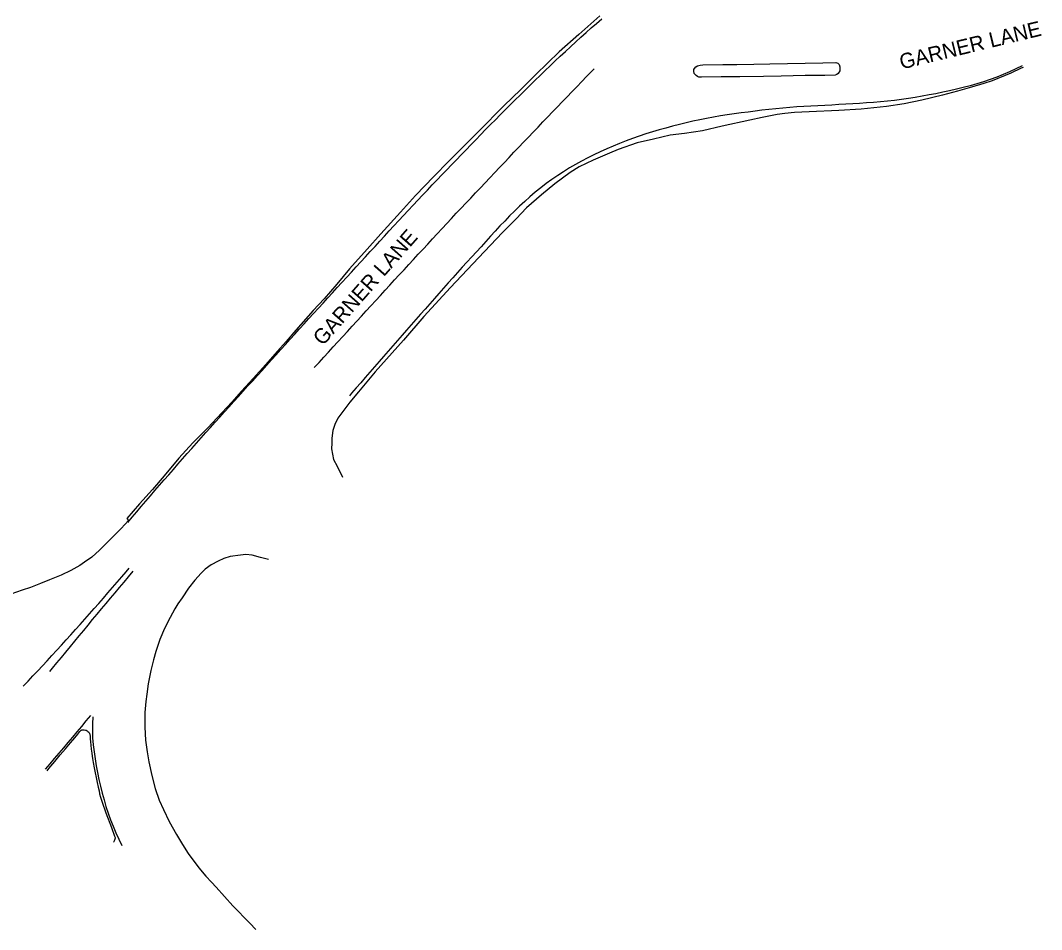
# Model space of a CAD drawing. Extents: x 1961683 to 1977751, y 798292 to 805767.
# Drawn here: x 1971882.7 to 1972247.5, y 802391.1 to 802715.6 of the extents above; entities that cross this region are included whole.
import ezdxf

# ---------------------------------------------------------------- set-up
doc = ezdxf.new("R2010")
doc.units = 0
for name, color, linetype in [('RD_EX_Conc', 7, 'Continuous'), ('RD_EX_Road', 7, 'Continuous'), ('RD_EX_Road_Paint', 7, 'Continuous'), ('RD_TX_RoadID', 7, 'Continuous')]:
    doc.layers.add(name, color=color, linetype=linetype)

msp = doc.modelspace()

# ---------------------------------------------------------------- linework, layer by layer
at = {"layer": 'RD_EX_Conc'}
for points in [[(1972150.42, 802700.16), (1972169.39, 802700.53), (1972173.93, 802700.6), (1972174.63, 802700.35), (1972175.13, 802699.87), (1972175.45, 802699), (1972175.42, 802697.57), (1972174.81, 802696.62), (1972174.29, 802696.26), (1972173.7, 802696.08), (1972170.04, 802695.96), (1972163.06, 802695.9), (1972154.48, 802695.75), (1972148.1, 802695.65), (1972139.65, 802695.51), (1972132.99, 802695.44), (1972125.99, 802695.32), (1972125.09, 802695.42), (1972124.51, 802695.65), (1972124.05, 802695.95), (1972123.69, 802696.26), (1972123.36, 802696.64), (1972123.2, 802697.56), (1972123.25, 802698.12), (1972123.48, 802698.51), (1972123.97, 802699.03), (1972124.56, 802699.39), (1972125.47, 802699.65), (1972126.52, 802699.79), (1972133.59, 802699.89), (1972138.58, 802699.94), (1972144.63, 802700.05), (1972150.42, 802700.16)], [(1971892.27, 802447.78), (1971892.93, 802448.58), (1971895.04, 802451.1), (1971896.99, 802453.42), (1971898.83, 802455.59), (1971900.59, 802457.67), (1971902.12, 802459.48), (1971903.25, 802460.87), (1971904, 802461.77), (1971904.37, 802462.16), (1971904.46, 802462.22), (1971904.57, 802462.27), (1971904.68, 802462.31), (1971904.81, 802462.33), (1971905.12, 802462.35), (1971905.54, 802462.34), (1971905.93, 802462.29), (1971906.07, 802462.26), (1971906.18, 802462.23), (1971906.28, 802462.19), (1971906.54, 802462.03), (1971906.86, 802461.79), (1971907.12, 802461.54), (1971907.31, 802461.28), (1971907.45, 802461.02), (1971907.51, 802460.88), (1971907.56, 802460.71), (1971907.64, 802460.09), (1971907.69, 802459.16), (1971907.78, 802458.07), (1971907.89, 802456.84), (1971908.03, 802455.49), (1971908.2, 802454.07), (1971908.34, 802452.95), (1971908.48, 802452.07), (1971908.72, 802450.71), (1971909.05, 802448.84), (1971909.41, 802447.02), (1971909.79, 802445.31), (1971910.17, 802443.58), (1971910.54, 802441.87), (1971910.82, 802440.55), (1971911.03, 802439.56), (1971911.34, 802438.33), (1971911.88, 802436.51), (1971913.24, 802432.77), (1971915.26, 802427.5), (1971916.4, 802424.45), (1971916.55, 802423.98), (1971916.53, 802423.71), (1971916.47, 802423.33), (1971916.36, 802422.93), (1971916.28, 802422.75), (1971916.19, 802422.59), (1971916.08, 802422.42), (1971915.93, 802422.26)]]:
    msp.add_lwpolyline(points, dxfattribs=at)
at = {"layer": 'RD_EX_Road'}
for points in [[(1972089.73, 802717.27), (1972082.21, 802710.64), (1972075.12, 802704.38), (1972066.86, 802696.35), (1972061.44, 802690.94), (1972055.38, 802685.15), (1972046.52, 802676.14), (1972041.26, 802670.85), (1972035.73, 802665.36), (1972030.45, 802659.9), (1972023.89, 802653.11), (1972018.52, 802647.16), (1972011.47, 802639.43), (1972006.53, 802633.94), (1972000.33, 802626.97), (1971995.74, 802621.41), (1971991.24, 802616.28), (1971987.32, 802612.05), (1971981.09, 802604.99), (1971977.62, 802601), (1971974.41, 802597.42), (1971970.4, 802592.81), (1971965.83, 802587.79), (1971961.76, 802583.21), (1971958.22, 802579.29), (1971954.73, 802575.5), (1971949.67, 802570.21), (1971944.27, 802564.78), (1971939.35, 802559.29), (1971934.13, 802552.99), (1971929.96, 802548.17), (1971925.27, 802543), (1971920.74, 802537.76), (1971921.36, 802537.08), (1971918.74, 802534.18), (1971914.59, 802530.02), (1971911.02, 802526.5), (1971908.26, 802524.03), (1971905.66, 802522.22), (1971904, 802521.07), (1971900.69, 802519.2), (1971897.34, 802517.6), (1971893.13, 802515.87), (1971889.91, 802514.62), (1971886.37, 802513.22), (1971883.34, 802512.23), (1971879.33, 802510.83)], [(1972240.83, 802698.83), (1972240.22, 802698.52), (1972236.48, 802696.75), (1972229.76, 802694.1), (1972226.8, 802693.07), (1972222.41, 802691.75), (1972217.42, 802690.37), (1972212.12, 802688.92), (1972204.72, 802687.15), (1972198.34, 802685.84), (1972192.13, 802684.88), (1972183.02, 802683.98), (1972175.09, 802683.45), (1972164.46, 802683.01), (1972159.24, 802682.73), (1972155.78, 802682.43), (1972153.02, 802682.07), (1972147.61, 802681), (1972143.25, 802680), (1972133.33, 802677.9), (1972126.35, 802676.26), (1972119.88, 802675.2), (1972114.8, 802674.67), (1972108.81, 802673.19), (1972103.06, 802671.89), (1972096.25, 802669.57), (1972093.16, 802668.19), (1972087.33, 802665.7), (1972082.26, 802663.32), (1972079.11, 802661.33), (1972073.65, 802657.27), (1972068.86, 802653.4), (1972063.52, 802648.66), (1972059.77, 802644.82), (1972054.97, 802639.85), (1972046.35, 802630.89), (1972036.29, 802620.31), (1972026.86, 802609.9), (1972019.52, 802601.5), (1972009.49, 802590.17), (1972003.48, 802583.02), (1972000.42, 802579.3), (1971998.62, 802576.99), (1971996.16, 802573.61), (1971995.04, 802571.42), (1971994.37, 802569.23), (1971993.91, 802566.46), (1971993.91, 802564.74), (1971993.89, 802562.63), (1971994.53, 802558.87), (1971995.86, 802556.45), (1971997.75, 802552.59)], [(1971971.38, 802523.13), (1971968.49, 802523.87), (1971965.46, 802524.69), (1971963.19, 802524.98), (1971961.35, 802524.77), (1971957.65, 802524.21), (1971955.45, 802523.51), (1971953.31, 802522.59), (1971950.86, 802521.24), (1971948.68, 802519.71), (1971947.27, 802518.3), (1971944.98, 802515.81), (1971942.77, 802512.91), (1971940.46, 802509.54), (1971939, 802507.31), (1971937.9, 802505.51), (1971936.18, 802502.43), (1971934.22, 802498.52), (1971932.59, 802494.67), (1971931.14, 802490.38), (1971930.3, 802487.36), (1971929.37, 802483.6), (1971928.37, 802478.82), (1971927.83, 802475.05), (1971927.52, 802472.45), (1971927.23, 802468.58), (1971927.19, 802463.35), (1971927.46, 802458.66), (1971928, 802454.53), (1971928.6, 802450.92), (1971929.71, 802446.07), (1971930.89, 802441.39), (1971932.27, 802437.3), (1971933.81, 802433.87), (1971935.85, 802429.69), (1971938.49, 802424.94), (1971940.58, 802421.42), (1971942.7, 802418.19), (1971946.45, 802413.14), (1971948.98, 802410.07), (1971951.01, 802407.98), (1971952.64, 802406.18), (1971958.66, 802399.51), (1971964.69, 802393.35), (1971966.82, 802391.06)]]:
    msp.add_lwpolyline(points, dxfattribs=at)
at = {"layer": 'RD_EX_Road_Paint'}
for points in [[(1971921.1, 802536.35), (1971922.7, 802538.27), (1971924.31, 802540.19), (1971925.91, 802542.11), (1971927.53, 802544.01), (1971929.15, 802545.91), (1971930.79, 802547.8), (1971932.44, 802549.68), (1971934.08, 802551.56), (1971935.73, 802553.44), (1971937.37, 802555.32), (1971939.01, 802557.21), (1971940.66, 802559.09), (1971942.3, 802560.97), (1971943.94, 802562.85), (1971945.59, 802564.73), (1971947.25, 802566.6), (1971948.92, 802568.46), (1971950.58, 802570.33), (1971952.25, 802572.18), (1971953.93, 802574.03), (1971955.62, 802575.87), (1971957.3, 802577.72), (1971958.99, 802579.57), (1971960.67, 802581.41), (1971962.35, 802583.26), (1971964.02, 802585.12), (1971965.69, 802586.97), (1971967.36, 802588.83), (1971969.03, 802590.69), (1971970.7, 802592.54), (1971972.37, 802594.4), (1971974.04, 802596.25), (1971975.72, 802598.1), (1971977.4, 802599.95), (1971979.08, 802601.8), (1971980.75, 802603.65), (1971982.43, 802605.49), (1971984.11, 802607.34), (1971985.79, 802609.19), (1971987.47, 802611.03), (1971989.15, 802612.88), (1971990.84, 802614.72), (1971992.52, 802616.56), (1971994.21, 802618.4), (1971995.9, 802620.24), (1971997.58, 802622.08), (1971999.27, 802623.92), (1972000.96, 802625.76), (1972002.64, 802627.6), (1972004.33, 802629.44), (1972006.01, 802631.28), (1972007.7, 802633.12), (1972009.39, 802634.96), (1972011.07, 802636.8), (1972012.76, 802638.64), (1972014.44, 802640.48), (1972016.14, 802642.32), (1972017.84, 802644.14), (1972019.55, 802645.96), (1972021.25, 802647.78), (1972022.96, 802649.61), (1972024.66, 802651.43), (1972026.37, 802653.25), (1972028.08, 802655.06), (1972029.81, 802656.87), (1972031.54, 802658.67), (1972033.27, 802660.47), (1972034.99, 802662.27), (1972036.72, 802664.07), (1972038.45, 802665.87), (1972040.19, 802667.67), (1972041.92, 802669.46), (1972043.66, 802671.25), (1972045.39, 802673.05), (1972047.13, 802674.84), (1972048.86, 802676.64), (1972050.62, 802678.41), (1972052.38, 802680.19), (1972054.13, 802681.96), (1972055.91, 802683.71), (1972057.69, 802685.46), (1972059.46, 802687.22), (1972061.24, 802688.97), (1972063.01, 802690.72), (1972064.78, 802692.48), (1972066.56, 802694.24), (1972068.35, 802695.97), (1972070.14, 802697.71), (1972071.94, 802699.44), (1972073.74, 802701.16), (1972075.55, 802702.89), (1972077.39, 802704.57), (1972079.23, 802706.25), (1972081.08, 802707.93), (1972082.93, 802709.6), (1972084.79, 802711.27), (1972086.64, 802712.94), (1972088.53, 802714.58), (1972090.41, 802716.22)], [(1972240.56, 802699.36), (1972238.3, 802698.29), (1972236.03, 802697.25), (1972233.74, 802696.27), (1972231.42, 802695.33), (1972229.07, 802694.48), (1972226.7, 802693.7), (1972224.31, 802692.96), (1972221.9, 802692.31), (1972219.48, 802691.67), (1972217.06, 802691.08), (1972214.62, 802690.53), (1972212.18, 802690), (1972209.73, 802689.47), (1972207.28, 802689), (1972204.82, 802688.53), (1972202.35, 802688.15), (1972199.88, 802687.77), (1972197.41, 802687.42), (1972194.93, 802687.08), (1972192.45, 802686.79), (1972189.96, 802686.52), (1972187.47, 802686.33), (1972184.98, 802686.16), (1972182.48, 802686), (1972179.99, 802685.85), (1972177.49, 802685.7), (1972175, 802685.55), (1972172.5, 802685.41), (1972170.01, 802685.27), (1972167.51, 802685.14), (1972165.01, 802685.01), (1972162.52, 802684.87), (1972160.02, 802684.72), (1972157.53, 802684.55), (1972155.04, 802684.31), (1972152.56, 802684.07), (1972150.07, 802683.8), (1972147.59, 802683.53), (1972145.11, 802683.22), (1972142.63, 802682.91), (1972140.15, 802682.6), (1972137.68, 802682.26), (1972135.21, 802681.92), (1972132.74, 802681.5), (1972130.28, 802681.08), (1972127.83, 802680.61), (1972125.39, 802680.12), (1972122.95, 802679.6), (1972120.52, 802679.04), (1972118.1, 802678.44), (1972115.68, 802677.83), (1972113.26, 802677.21), (1972110.86, 802676.56), (1972108.47, 802675.83), (1972106.09, 802675.09), (1972103.73, 802674.29), (1972101.38, 802673.46), (1972099.05, 802672.58), (1972096.73, 802671.67), (1972094.42, 802670.72), (1972092.13, 802669.74), (1972089.85, 802668.73), (1972087.59, 802667.69), (1972085.35, 802666.59), (1972083.15, 802665.42), (1972080.96, 802664.22), (1972078.8, 802662.97), (1972076.71, 802661.6), (1972074.64, 802660.22), (1972072.56, 802658.83), (1972070.55, 802657.35), (1972068.58, 802655.82), (1972066.63, 802654.27), (1972064.73, 802652.66), (1972062.86, 802651), (1972061.03, 802649.31), (1972059.25, 802647.56), (1972057.48, 802645.8), (1972055.74, 802644.01), (1972054, 802642.23), (1972052.3, 802640.4), (1972050.63, 802638.55), (1972048.95, 802636.7), (1972047.27, 802634.85), (1972045.59, 802633.01), (1972043.91, 802631.17), (1972042.23, 802629.32), (1972040.55, 802627.48), (1972038.87, 802625.63), (1972037.22, 802623.77), (1972035.56, 802621.9), (1972033.9, 802620.04), (1972032.24, 802618.18), (1972030.58, 802616.31), (1972028.93, 802614.44), (1972027.28, 802612.57), (1972025.63, 802610.7), (1972023.98, 802608.83), (1972022.33, 802606.96), (1972020.68, 802605.09), (1972019.03, 802603.22), (1972017.38, 802601.35), (1972015.74, 802599.46), (1972014.11, 802597.58), (1972012.47, 802595.7), (1972010.83, 802593.82), (1972009.19, 802591.93), (1972007.56, 802590.05), (1972005.92, 802588.17), (1972004.28, 802586.29), (1972002.64, 802584.4), (1972001.01, 802582.52), (1972000.23, 802581.63)], [(1971987.71, 802591.71), (1971989.4, 802593.55), (1971991.09, 802595.39), (1971992.77, 802597.23), (1971994.46, 802599.07), (1971996.15, 802600.91), (1971997.84, 802602.75), (1971999.52, 802604.59), (1972001.21, 802606.42), (1972002.89, 802608.26), (1972004.58, 802610.1), (1972006.27, 802611.94), (1972007.95, 802613.78), (1972009.64, 802615.62), (1972011.32, 802617.46), (1972013.01, 802619.29), (1972014.7, 802621.13), (1972016.38, 802622.97), (1972018.07, 802624.81), (1972019.76, 802626.64), (1972021.46, 802628.48), (1972023.16, 802630.31), (1972024.85, 802632.14), (1972026.55, 802633.97), (1972028.25, 802635.8), (1972029.94, 802637.63), (1972031.64, 802639.46), (1972033.33, 802641.29), (1972035.03, 802643.12), (1972036.73, 802644.95), (1972038.43, 802646.77), (1972040.15, 802648.59), (1972041.86, 802650.4), (1972043.58, 802652.21), (1972045.29, 802654.02), (1972047.01, 802655.84), (1972048.73, 802657.65), (1972050.44, 802659.46), (1972052.16, 802661.28), (1972053.88, 802663.09), (1972055.59, 802664.9), (1972057.31, 802666.72), (1972059.02, 802668.53), (1972060.74, 802670.34), (1972062.46, 802672.15), (1972064.17, 802673.97), (1972065.89, 802675.77), (1972067.62, 802677.57), (1972069.35, 802679.37), (1972071.08, 802681.17), (1972072.81, 802682.97), (1972074.54, 802684.77), (1972076.27, 802686.57), (1972078, 802688.36), (1972079.73, 802690.16), (1972081.46, 802691.96), (1972083.2, 802693.76), (1972084.93, 802695.56), (1972086.65, 802697.36), (1972087.61, 802698.35)], [(1971883.76, 802477.95), (1971885.48, 802479.77), (1971887.19, 802481.59), (1971888.9, 802483.41), (1971890.62, 802485.23), (1971892.33, 802487.05), (1971894.01, 802488.9), (1971895.7, 802490.75), (1971897.38, 802492.6), (1971899.06, 802494.44), (1971900.75, 802496.29), (1971902.42, 802498.15), (1971904.08, 802500.02), (1971905.74, 802501.88), (1971907.41, 802503.75), (1971909.07, 802505.62), (1971910.73, 802507.49), (1971912.37, 802509.38), (1971914, 802511.27), (1971915.64, 802513.16), (1971917.28, 802515.05), (1971918.91, 802516.93), (1971920.55, 802518.82), (1971921.61, 802520.05)], [(1971922.84, 802518.95), (1971921.24, 802517.04), (1971919.63, 802515.12), (1971918.03, 802513.2), (1971916.42, 802511.28), (1971914.82, 802509.37), (1971913.21, 802507.45), (1971911.61, 802505.53), (1971910, 802503.62), (1971908.4, 802501.7), (1971906.8, 802499.78), (1971905.21, 802497.85), (1971903.62, 802495.92), (1971902.03, 802493.99), (1971900.45, 802492.06), (1971898.86, 802490.13), (1971897.27, 802488.2), (1971895.68, 802486.27), (1971894.09, 802484.34), (1971893.14, 802483.19)], [(1971907.74, 802467.43), (1971906.13, 802465.52), (1971904.52, 802463.61), (1971902.91, 802461.69), (1971901.3, 802459.78), (1971899.69, 802457.87), (1971898.07, 802455.96), (1971896.45, 802454.06), (1971894.84, 802452.15), (1971893.22, 802450.24), (1971891.6, 802448.34)], [(1971908.65, 802466.95), (1971908.51, 802464.45), (1971908.46, 802461.96), (1971908.53, 802459.46), (1971908.76, 802456.97), (1971909.03, 802454.48), (1971909.39, 802452.01), (1971909.79, 802449.54), (1971910.25, 802447.08), (1971910.78, 802444.64), (1971911.35, 802442.21), (1971911.92, 802439.77), (1971912.61, 802437.37), (1971913.3, 802434.97), (1971914.11, 802432.6), (1971914.96, 802430.25), (1971915.87, 802427.92), (1971916.83, 802425.61), (1971917.91, 802423.36), (1971918.98, 802421.11)]]:
    msp.add_lwpolyline(points, dxfattribs=at)

# ---------------------------------------------------------------- texts
at = {"layer": 'RD_TX_RoadID'}
for rotation, p in [(13.5828, (1972197.44, 802698.11)), (48.6019, (1971990.76, 802599.2))]:
    msp.add_text('GARNER LANE', height=5.4, rotation=rotation, dxfattribs=at).set_placement(p)

doc.saveas('drawing.dxf')
